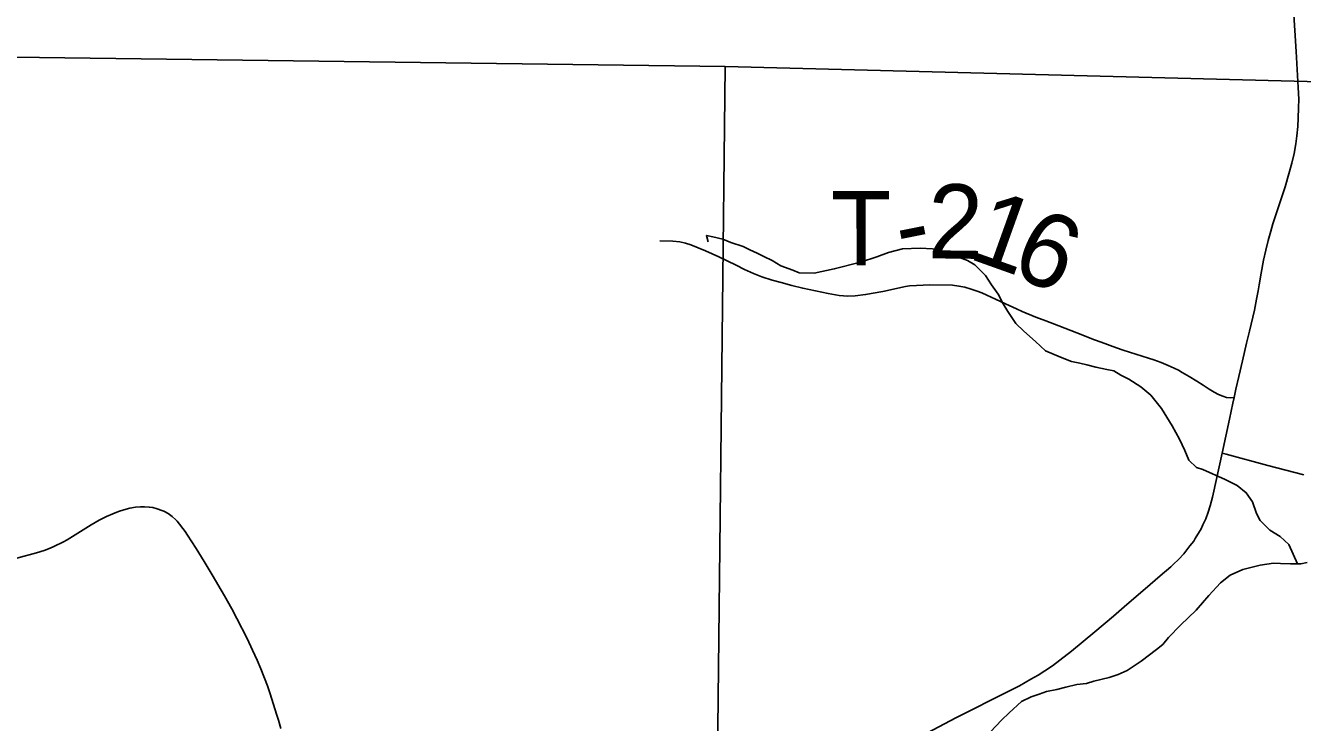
# Model space of a CAD drawing. Extents: x -7.1 to 34, y 0 to 22.
# Drawn here: x 4.122 to 5.098, y 16.285 to 16.818 of the extents above; entities that cross this region are included whole.
import ezdxf

# ---------------------------------------------------------------- set-up
doc = ezdxf.new("R2010")
doc.units = 0
for name, color, linetype in [('GM_X_County_Road', 7, 'Continuous'), ('GM_X_Minor_River', 7, 'Continuous'), ('GM_X_Section', 7, 'Continuous'), ('GM_X_Township_Road', 7, 'Continuous'), ('GM_X_Township_Road_Text', 7, 'Continuous')]:
    doc.layers.add(name, color=color, linetype=linetype)

msp = doc.modelspace()

# ---------------------------------------------------------------- linework, layer by layer
at = {"layer": 'GM_X_County_Road'}
for points in [[(5.04533, 16.53376), (5.0468, 16.54028), (5.049, 16.54998), (5.05173, 16.56192), (5.05494, 16.57542), (5.05707, 16.5845), (5.0609, 16.60054), (5.06261, 16.60907), (5.06374, 16.61531), (5.06445, 16.61986), (5.06602, 16.6288), (5.06786, 16.63888), (5.06957, 16.64655), (5.07141, 16.65393), (5.0734, 16.66089), (5.0751, 16.66657), (5.07809, 16.67565), (5.08092, 16.68404), (5.08433, 16.69497), (5.08717, 16.70477), (5.08948, 16.71296), (5.09118, 16.72035), (5.09243, 16.72763), (5.09328, 16.73387), (5.09399, 16.74097), (5.09441, 16.74736), (5.0947, 16.75517), (5.09484, 16.76184), (5.09441, 16.77079), (5.09286, 16.7982), (5.09087, 16.83043)], [(5.03627, 16.49118), (5.04181, 16.5174), (5.0444, 16.52955), (5.04533, 16.53376)], [(4.81115, 16.27752), (4.83273, 16.28888), (4.84196, 16.29357), (4.86405, 16.30477), (4.8813, 16.31351), (4.88583, 16.31601), (4.89003, 16.31842), (4.89556, 16.32159), (4.90071, 16.32482), (4.90659, 16.32881), (4.91225, 16.33304), (4.92106, 16.34), (4.93892, 16.35479), (4.95314, 16.3667), (4.9635, 16.37564), (4.97732, 16.38749), (4.98887, 16.3974), (4.99698, 16.40436), (4.99906, 16.40632), (5.00297, 16.41), (5.00692, 16.41443), (5.00857, 16.41634), (5.01164, 16.42036), (5.01456, 16.42412), (5.01575, 16.42593), (5.02014, 16.43356), (5.02157, 16.43645), (5.02368, 16.4412), (5.02556, 16.44619), (5.02716, 16.45114), (5.0289, 16.45759), (5.02992, 16.46221), (5.03123, 16.46807), (5.03402, 16.48092), (5.03627, 16.49118)], [(4.11522, 16.41102), (4.13017, 16.41511), (4.13603, 16.41695), (4.14069, 16.41863), (4.14359, 16.41984), (4.15098, 16.42355), (4.15382, 16.42514), (4.17213, 16.43645), (4.17822, 16.44014), (4.18369, 16.44293), (4.18873, 16.44503), (4.19289, 16.44664), (4.19708, 16.44801), (4.2017, 16.44918), (4.20589, 16.44989), (4.20966, 16.45024), (4.21285, 16.45033), (4.21642, 16.45012), (4.21926, 16.44964), (4.22249, 16.44882), (4.22603, 16.44757), (4.22758, 16.44685), (4.23092, 16.44509), (4.23396, 16.44293), (4.23668, 16.44045), (4.23772, 16.43932), (4.24376, 16.4314), (4.24574, 16.42852), (4.25216, 16.41849), (4.25834, 16.40842), (4.26451, 16.39823), (4.274, 16.38216), (4.27948, 16.37235), (4.28335, 16.36485), (4.29123, 16.34961), (4.29541, 16.34059), (4.29884, 16.33298), (4.30177, 16.32645), (4.30682, 16.31345), (4.30867, 16.3082), (4.314, 16.29097), (4.31514, 16.28715), (4.31691, 16.2809)]]:
    msp.add_lwpolyline(points, dxfattribs=at)
at = {"layer": 'GM_X_Minor_River'}
for points in [[(5.09377, 16.40675), (5.0871, 16.4215), (5.08058, 16.4275), (5.07256, 16.43232), (5.06526, 16.43983), (5.06253, 16.44512), (5.05937, 16.45421), (5.05473, 16.46099), (5.04783, 16.4666), (5.03868, 16.47103), (5.02153, 16.47877), (5.01659, 16.48022), (5.01083, 16.48584), (5.00769, 16.49341), (5.00378, 16.50211), (4.99795, 16.5123), (4.98981, 16.5255), (4.98171, 16.53566), (4.97405, 16.54202), (4.96488, 16.54797), (4.95878, 16.55093), (4.95343, 16.55427), (4.94811, 16.55533), (4.93975, 16.55711), (4.93292, 16.55891), (4.9276, 16.55997), (4.92114, 16.5614), (4.91276, 16.5647), (4.90134, 16.56948), (4.89366, 16.5766), (4.88484, 16.58446), (4.8787, 16.59046), (4.87251, 16.5995), (4.86901, 16.60554), (4.86512, 16.61272), (4.8601, 16.61987), (4.85545, 16.62704), (4.84738, 16.63529), (4.84165, 16.63863), (4.8348, 16.64119), (4.82681, 16.64412), (4.81996, 16.6463), (4.81502, 16.64737), (4.80555, 16.64799), (4.79193, 16.6474), (4.78137, 16.64458), (4.77232, 16.6414), (4.75989, 16.6374), (4.7399, 16.63215), (4.72442, 16.62887), (4.71306, 16.62908), (4.70811, 16.63129), (4.69897, 16.63458), (4.69248, 16.63867), (4.686, 16.64162), (4.68104, 16.64421), (4.67532, 16.64679), (4.67036, 16.64938), (4.66085, 16.65228), (4.65476, 16.65486), (4.64716, 16.65664), (4.64222, 16.65771), (4.64343, 16.65278)], [(5.10131, 16.40763), (5.0964, 16.40679), (5.08845, 16.40668), (5.08088, 16.40694), (5.07557, 16.40725), (5.06537, 16.40557), (5.05217, 16.40233), (5.04239, 16.39799), (5.0349, 16.39217), (5.02595, 16.38252), (5.01627, 16.37134), (5.00432, 16.35974), (4.99537, 16.35047), (4.99091, 16.34507), (4.98604, 16.34119), (4.97443, 16.33226), (4.96356, 16.32525), (4.95679, 16.3221), (4.95, 16.31972), (4.93831, 16.31688), (4.93265, 16.31527), (4.9251, 16.3144), (4.91679, 16.31237), (4.91, 16.31074), (4.90208, 16.3091), (4.89642, 16.30711), (4.8904, 16.30512), (4.88288, 16.30158), (4.87354, 16.29268), (4.86756, 16.28727), (4.85936, 16.27839)]]:
    msp.add_lwpolyline(points, dxfattribs=at)
at = {"layer": 'GM_X_Section'}
for points in [[(3.82173, 16.79779), (4.6565, 16.78681), (4.64501, 15.75231), (3.80727, 15.75945), (3.82053, 16.67232)], [(4.6565, 16.78681), (5.67419, 16.76067), (5.65687, 15.73556), (4.64501, 15.75231)]]:
    msp.add_lwpolyline(points, close=True, dxfattribs=at)
at = {"layer": 'GM_X_Township_Road'}
for points in [[(4.60666, 16.65365), (4.61656, 16.6533), (4.62186, 16.65273), (4.62611, 16.65181), (4.63038, 16.65043), (4.64151, 16.64598), (4.65178, 16.64133), (4.66491, 16.63489), (4.67135, 16.63178), (4.67803, 16.62855), (4.68448, 16.62614), (4.69254, 16.6236), (4.69926, 16.62171), (4.70741, 16.61943), (4.71579, 16.61739), (4.73524, 16.61324), (4.74365, 16.61186), (4.75032, 16.61129), (4.75596, 16.61152), (4.76379, 16.61255), (4.77691, 16.61485), (4.79428, 16.61866), (4.79747, 16.61913), (4.80276, 16.61955), (4.80789, 16.61981), (4.81241, 16.61999), (4.8301, 16.61969), (4.83505, 16.619), (4.83965, 16.61808), (4.84442, 16.61672), (4.84897, 16.61513), (4.85272, 16.61375), (4.85653, 16.61212), (4.8631, 16.60907), (4.87063, 16.60548), (4.87899, 16.60151), (4.88342, 16.59956), (4.89376, 16.59532), (4.90145, 16.59231), (4.91136, 16.58851), (4.92515, 16.58329), (4.93877, 16.57799), (4.94381, 16.57604), (4.9554, 16.5718), (4.96061, 16.57003), (4.98005, 16.56394), (4.98414, 16.56265), (4.9897, 16.56056), (4.99501, 16.55836), (4.99961, 16.55632), (5.00279, 16.55473), (5.00579, 16.55305), (5.01098, 16.54993), (5.01694, 16.54635), (5.0218, 16.54323), (5.0264, 16.54032), (5.03003, 16.53802), (5.03348, 16.53608), (5.03666, 16.53475), (5.03967, 16.53395), (5.04267, 16.53368), (5.04533, 16.53376)], [(5.04533, 16.53376), (5.0444, 16.52955), (5.04181, 16.5174), (5.03627, 16.49118)], [(5.03627, 16.49118), (5.03921, 16.49041), (5.07105, 16.48184), (5.09879, 16.47467)]]:
    msp.add_lwpolyline(points, dxfattribs=at)

# ---------------------------------------------------------------- texts
at = {"layer": 'GM_X_Township_Road_Text'}
for s, rotation, p in [('2', 359.2538, (4.81113, 16.64026)), ('T', 0.14211, (4.73726, 16.63477)), ('1', 340.31708, (4.84099, 16.64069)), ('6', 335.4659, (4.8725, 16.62947)), ('-', 11.20747, (4.79156, 16.63605))]:
    msp.add_text(s, height=0.05682, rotation=rotation, dxfattribs=at).set_placement(p)

doc.saveas('drawing.dxf')
